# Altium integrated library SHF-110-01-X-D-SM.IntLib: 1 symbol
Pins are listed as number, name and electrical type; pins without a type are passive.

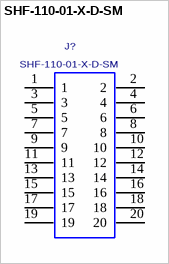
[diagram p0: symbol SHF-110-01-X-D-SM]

## SHF-110-01-X-D-SM
designator J?
0.05"X0.05" SHROUDED TERMINAL STRIP, 20PINS.; MANUFACTURER: SAMTEC
footprint SHF-110-01-X-D-SM
pins: 1, 2, 3, 4, 5, 6, 7, 8, 9, 10, 11, 12, 13, 14, 15, 16, 17, 18, 19, 20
